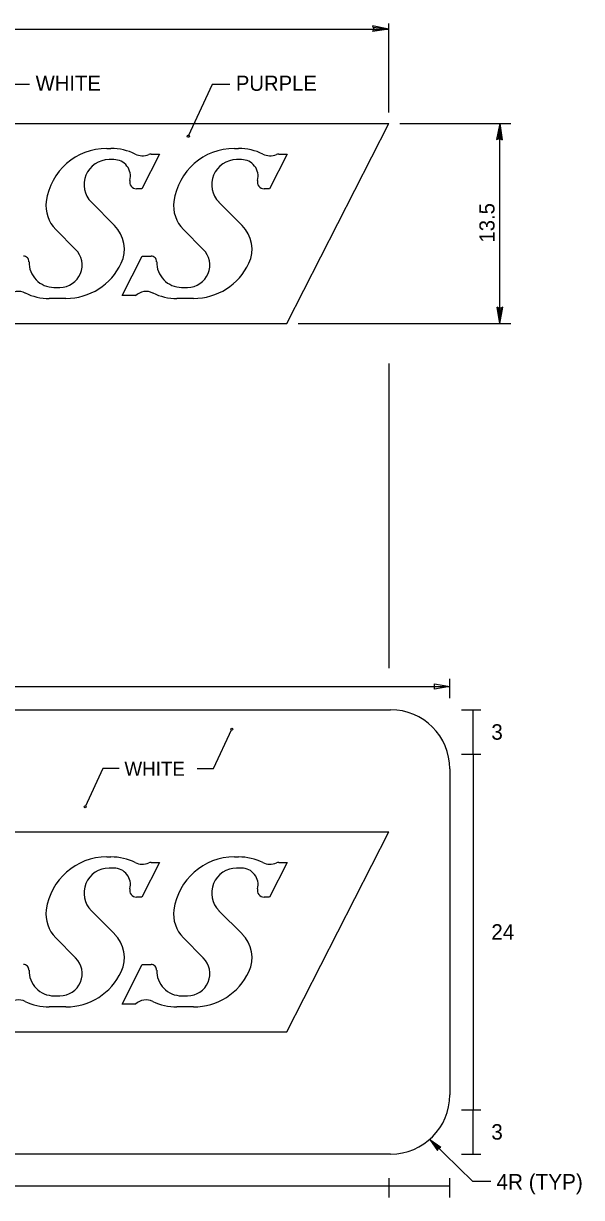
# Model space of a CAD drawing. Extents: x 10268197 to 10268826, y 2141503 to 2142677.
# Drawn here: x 10268633.6 to 10268655.85, y 2142371.58 to 2142418.33 of the extents above; entities that cross this region are included whole.
import ezdxf

# ---------------------------------------------------------------- set-up
doc = ezdxf.new("R2010")
doc.units = 0
for name, color, linetype in [('1', 7, 'Continuous'), ('21', 7, 'Continuous'), ('Default', 7, 'Continuous'), ('GSBWFill', 7, 'Continuous'), ('GSDims', 7, 'Continuous')]:
    doc.layers.add(name, color=color, linetype=linetype)

msp = doc.modelspace()

# ---------------------------------------------------------------- linework, layer by layer
at = {"layer": '1'}
for p, q in [((10268648.163, 2142414.794), (10268648.163, 2142418.333)), ((10268628.963, 2142418.112), (10268648.163, 2142418.112)), ((10268633.85, 2142415.902), (10268633.148, 2142415.902)), ((10268641.128, 2142415.902), (10268640.174, 2142413.844)), ((10268641.831, 2142415.902), (10268641.128, 2142415.902)), ((10268648.606, 2142414.351), (10268653.03, 2142414.351)), ((10268652.587, 2142406.387), (10268652.587, 2142414.351)), ((10268644.548, 2142406.387), (10268653.03, 2142406.387)), ((10268648.163, 2142404.795), (10268648.163, 2142392.661)), ((10268641.183, 2142388.664), (10268641.909, 2142390.23)), ((10268636.768, 2142388.664), (10268636.06, 2142387.136)), ((10268637.425, 2142388.664), (10268636.768, 2142388.664)), ((10268640.526, 2142388.664), (10268641.183, 2142388.664)), ((10268651.509, 2142372.214), (10268649.797, 2142373.894)), ((10268652.234, 2142372.214), (10268651.509, 2142372.214))]:
    msp.add_line(p, q, dxfattribs=at)
for centre, radius in [((10268640.175, 2142413.843), 0.0442), ((10268641.909, 2142390.23), 0.0414), ((10268636.06, 2142387.136), 0.0414)]:
    msp.add_circle(centre, radius, dxfattribs=at)
at = {"layer": '21'}
for p, q in [((10268649.797, 2142373.894), (10268650.243, 2142373.588)), ((10268649.797, 2142373.894), (10268650.111, 2142373.454)), ((10268649.797, 2142373.894), (10268650.13, 2142373.504)), ((10268649.797, 2142373.894), (10268650.193, 2142373.568)), ((10268650.111, 2142373.454), (10268650.148, 2142373.549)), ((10268650.148, 2142373.549), (10268650.243, 2142373.588))]:
    msp.add_line(p, q, dxfattribs=at)
at = {"layer": 'Default'}
for p, q in [((10268648.163, 2142418.112), (10268647.52, 2142418.237)), ((10268647.52, 2142418.237), (10268647.568, 2142418.122)), ((10268648.163, 2142418.112), (10268647.545, 2142418.177)), ((10268647.568, 2142418.122), (10268647.516, 2142418.009)), ((10268648.163, 2142418.112), (10268647.516, 2142418.009)), ((10268648.163, 2142418.112), (10268647.544, 2142418.068)), ((10268622.925, 2142414.351), (10268648.163, 2142414.351)), ((10268644.105, 2142406.387), (10268648.163, 2142414.351)), ((10268652.587, 2142414.351), (10268652.463, 2142413.708)), ((10268652.587, 2142414.351), (10268652.523, 2142413.733)), ((10268652.587, 2142414.351), (10268652.69, 2142413.704)), ((10268652.587, 2142414.351), (10268652.631, 2142413.732)), ((10268652.463, 2142413.708), (10268652.577, 2142413.755)), ((10268652.577, 2142413.755), (10268652.69, 2142413.704)), ((10268636.924, 2142413.355), (10268637.092, 2142413.355)), ((10268639.028, 2142413.134), (10268638.325, 2142411.754)), ((10268638.697, 2142413.134), (10268639.028, 2142413.134)), ((10268642.012, 2142413.355), (10268642.18, 2142413.355)), ((10268644.117, 2142413.134), (10268643.413, 2142411.754)), ((10268643.784, 2142413.134), (10268644.117, 2142413.134)), ((10268637.204, 2142412.913), (10268637.014, 2142412.913)), ((10268642.292, 2142412.913), (10268642.102, 2142412.913)), ((10268638.325, 2142411.754), (10268638.104, 2142411.754)), ((10268643.413, 2142411.754), (10268643.192, 2142411.754)), ((10268636.31, 2142411.214), (10268637.238, 2142410.286)), ((10268641.398, 2142411.214), (10268642.326, 2142410.286)), ((10268635.685, 2142409.336), (10268634.889, 2142410.132)), ((10268640.773, 2142409.336), (10268639.977, 2142410.132)), ((10268637.534, 2142407.494), (10268638.337, 2142409.07)), ((10268638.337, 2142409.07), (10268638.693, 2142409.07)), ((10268634.82, 2142407.825), (10268635.06, 2142407.825)), ((10268638.071, 2142407.494), (10268637.534, 2142407.494)), ((10268639.909, 2142407.825), (10268640.147, 2142407.825)), ((10268635.298, 2142407.382), (10268634.632, 2142407.382)), ((10268640.385, 2142407.382), (10268639.72, 2142407.382)), ((10268652.587, 2142406.387), (10268652.484, 2142407.034)), ((10268652.597, 2142406.983), (10268652.484, 2142407.034)), ((10268652.587, 2142406.387), (10268652.544, 2142407.007)), ((10268652.587, 2142406.387), (10268652.712, 2142407.03)), ((10268652.587, 2142406.387), (10268652.652, 2142407.005)), ((10268652.712, 2142407.03), (10268652.597, 2142406.983)), ((10268622.338, 2142406.387), (10268644.105, 2142406.387))]:
    msp.add_line(p, q, dxfattribs=at)
for centre, radius, start, end in [((10268636.924, 2142410.922), 2.433, 90, 172.3089), ((10268637.092, 2142411.143), 2.212, 64.0896, 90), ((10268638.348, 2142413.73), 0.664, 244.0896, 292.0347), ((10268638.697, 2142412.868), 0.265, 90, 112.0347), ((10268642.012, 2142410.922), 2.433, 90, 172.3089), ((10268642.179, 2142411.143), 2.212, 64.0896, 90), ((10268643.436, 2142413.73), 0.664, 244.0896, 292.0347), ((10268643.785, 2142412.868), 0.265, 90, 112.0347), ((10268637.014, 2142411.917), 0.995, 90, 225), ((10268637.204, 2142412.249), 0.664, 345.6915, 90), ((10268642.102, 2142411.917), 0.995, 90, 225), ((10268642.292, 2142412.249), 0.664, 345.6915, 90), ((10268638.104, 2142412.019), 0.265, 165.6915, 270), ((10268643.192, 2142412.019), 0.265, 165.6915, 270), ((10268635.828, 2142411.07), 1.327, 172.3089, 225), ((10268640.915, 2142411.07), 1.327, 172.3089, 225), ((10268636.299, 2142409.347), 1.327, 334.95, 45), ((10268641.387, 2142409.347), 1.327, 334.95, 45), ((10268635.059, 2142408.71), 0.885, 270, 45), ((10268640.147, 2142408.71), 0.885, 270, 45), ((10268633.604, 2142408.848), 0.221, 358.6664, 90), ((10268634.821, 2142408.82), 0.995, 178.6665, 270), ((10268638.692, 2142408.848), 0.221, 358.6664, 90), ((10268639.909, 2142408.82), 0.995, 178.6665, 270), ((10268635.297, 2142409.816), 2.433, 270, 334.95), ((10268640.385, 2142409.816), 2.433, 270, 334.95), ((10268633.407, 2142407.041), 0.619, 64.3795, 133.1892), ((10268634.632, 2142409.594), 2.212, 244.3795, 270), ((10268638.495, 2142407.041), 0.619, 64.3795, 133.1892), ((10268639.719, 2142409.594), 2.212, 244.3795, 270)]:
    msp.add_arc(centre, radius, start, end, dxfattribs=at)
at = {"layer": 'GSBWFill'}
for p, q in [((10268603.406, 2142391.003), (10268648.239, 2142391.003)), ((10268650.598, 2142388.644), (10268650.598, 2142375.666)), ((10268622.925, 2142386.137), (10268648.163, 2142386.137)), ((10268644.105, 2142378.174), (10268648.163, 2142386.137)), ((10268636.924, 2142385.142), (10268637.092, 2142385.142)), ((10268642.012, 2142385.142), (10268642.18, 2142385.142)), ((10268637.204, 2142384.699), (10268637.014, 2142384.699)), ((10268639.028, 2142384.92), (10268638.325, 2142383.541)), ((10268638.697, 2142384.92), (10268639.028, 2142384.92)), ((10268642.292, 2142384.699), (10268642.102, 2142384.699)), ((10268644.117, 2142384.92), (10268643.413, 2142383.541)), ((10268643.784, 2142384.92), (10268644.117, 2142384.92)), ((10268638.325, 2142383.541), (10268638.104, 2142383.541)), ((10268643.413, 2142383.541), (10268643.192, 2142383.541)), ((10268636.31, 2142383), (10268637.238, 2142382.073)), ((10268641.398, 2142383), (10268642.326, 2142382.073)), ((10268635.685, 2142381.122), (10268634.889, 2142381.918)), ((10268640.773, 2142381.122), (10268639.977, 2142381.918)), ((10268637.534, 2142379.28), (10268638.337, 2142380.857)), ((10268638.337, 2142380.857), (10268638.693, 2142380.857)), ((10268634.82, 2142379.611), (10268635.06, 2142379.611)), ((10268639.909, 2142379.611), (10268640.147, 2142379.611)), ((10268635.298, 2142379.169), (10268634.632, 2142379.169)), ((10268638.071, 2142379.28), (10268637.534, 2142379.28)), ((10268640.385, 2142379.169), (10268639.72, 2142379.169)), ((10268622.338, 2142378.174), (10268644.105, 2142378.174)), ((10268648.239, 2142373.306), (10268603.406, 2142373.306))]:
    msp.add_line(p, q, dxfattribs=at)
for centre, radius, start, end in [((10268648.239, 2142388.644), 2.36, 360, 90), ((10268636.924, 2142382.708), 2.433, 90, 172.3089), ((10268637.092, 2142382.929), 2.212, 64.0896, 90), ((10268642.012, 2142382.708), 2.433, 90, 172.3089), ((10268642.179, 2142382.929), 2.212, 64.0896, 90), ((10268637.014, 2142383.703), 0.995, 90, 225), ((10268637.204, 2142384.035), 0.664, 345.6915, 90), ((10268638.348, 2142385.516), 0.664, 244.0896, 292.0347), ((10268638.697, 2142384.654), 0.265, 90, 112.0347), ((10268642.102, 2142383.703), 0.995, 90, 225), ((10268642.292, 2142384.035), 0.664, 345.6915, 90), ((10268643.436, 2142385.516), 0.664, 244.0896, 292.0347), ((10268643.785, 2142384.654), 0.265, 90, 112.0347), ((10268638.104, 2142383.805), 0.265, 165.6915, 270), ((10268643.192, 2142383.805), 0.265, 165.6915, 270), ((10268635.828, 2142382.856), 1.327, 172.3089, 225), ((10268640.915, 2142382.856), 1.327, 172.3089, 225), ((10268636.299, 2142381.133), 1.327, 334.95, 45), ((10268641.387, 2142381.133), 1.327, 334.95, 45), ((10268633.604, 2142380.635), 0.221, 358.6664, 90), ((10268635.059, 2142380.496), 0.885, 270, 45), ((10268638.692, 2142380.635), 0.221, 358.6664, 90), ((10268640.147, 2142380.496), 0.885, 270, 45), ((10268634.821, 2142380.606), 0.995, 178.6664, 270), ((10268635.297, 2142381.602), 2.433, 270, 334.95), ((10268639.909, 2142380.606), 0.995, 178.6664, 270), ((10268640.385, 2142381.602), 2.433, 270, 334.95), ((10268633.407, 2142378.827), 0.619, 64.3795, 133.1892), ((10268634.632, 2142381.381), 2.212, 244.3795, 270), ((10268638.495, 2142378.827), 0.619, 64.3795, 133.1892), ((10268639.719, 2142381.381), 2.212, 244.3795, 270), ((10268648.239, 2142375.666), 2.36, 270, 360)]:
    msp.add_arc(centre, radius, start, end, dxfattribs=at)
at = {"layer": 'GSDims'}
for p, q in [((10268650.598, 2142391.465), (10268650.598, 2142392.235)), ((10268601.047, 2142391.927), (10268650.598, 2142391.927)), ((10268651.06, 2142391.003), (10268651.83, 2142391.003)), ((10268651.522, 2142389.234), (10268651.522, 2142391.003)), ((10268651.06, 2142389.234), (10268651.83, 2142389.234)), ((10268651.522, 2142389.234), (10268651.522, 2142375.076)), ((10268651.06, 2142375.076), (10268651.83, 2142375.076)), ((10268651.522, 2142373.306), (10268651.522, 2142375.076)), ((10268651.06, 2142373.306), (10268651.83, 2142373.306)), ((10268648.18, 2142371.577), (10268648.18, 2142372.347)), ((10268650.598, 2142371.577), (10268650.598, 2142372.347)), ((10268601.047, 2142372.039), (10268650.598, 2142372.039))]:
    msp.add_line(p, q, dxfattribs=at)
msp.add_lwpolyline([(10268650.598, 2142391.927), (10268649.982, 2142391.824), (10268649.982, 2142392.03)], close=True, dxfattribs=at)

# ---------------------------------------------------------------- texts
at = {"layer": '1'}
for s, height, p in [('WHITE', 0.6037, (10268634.09, 2142415.651)), ('PURPLE', 0.6037, (10268642.07, 2142415.651)), ('WHITE', 0.5597, (10268637.629, 2142388.374)), ('4R (TYP)', 0.6176, (10268652.458, 2142371.894))]:
    msp.add_text(s, height=height, dxfattribs=at).set_placement(p)
msp.add_text('13.5', height=0.6037, rotation=90, dxfattribs=at).set_placement((10268652.38, 2142409.609))
at = {"layer": 'GSDims'}
for s, height, p in [('3', 0.616, (10268652.252, 2142389.81)), ('24', 0.6159, (10268652.252, 2142381.847)), ('3', 0.616, (10268652.252, 2142373.883))]:
    msp.add_text(s, height=height, rotation=360, dxfattribs=at).set_placement(p)

doc.saveas('drawing.dxf')
